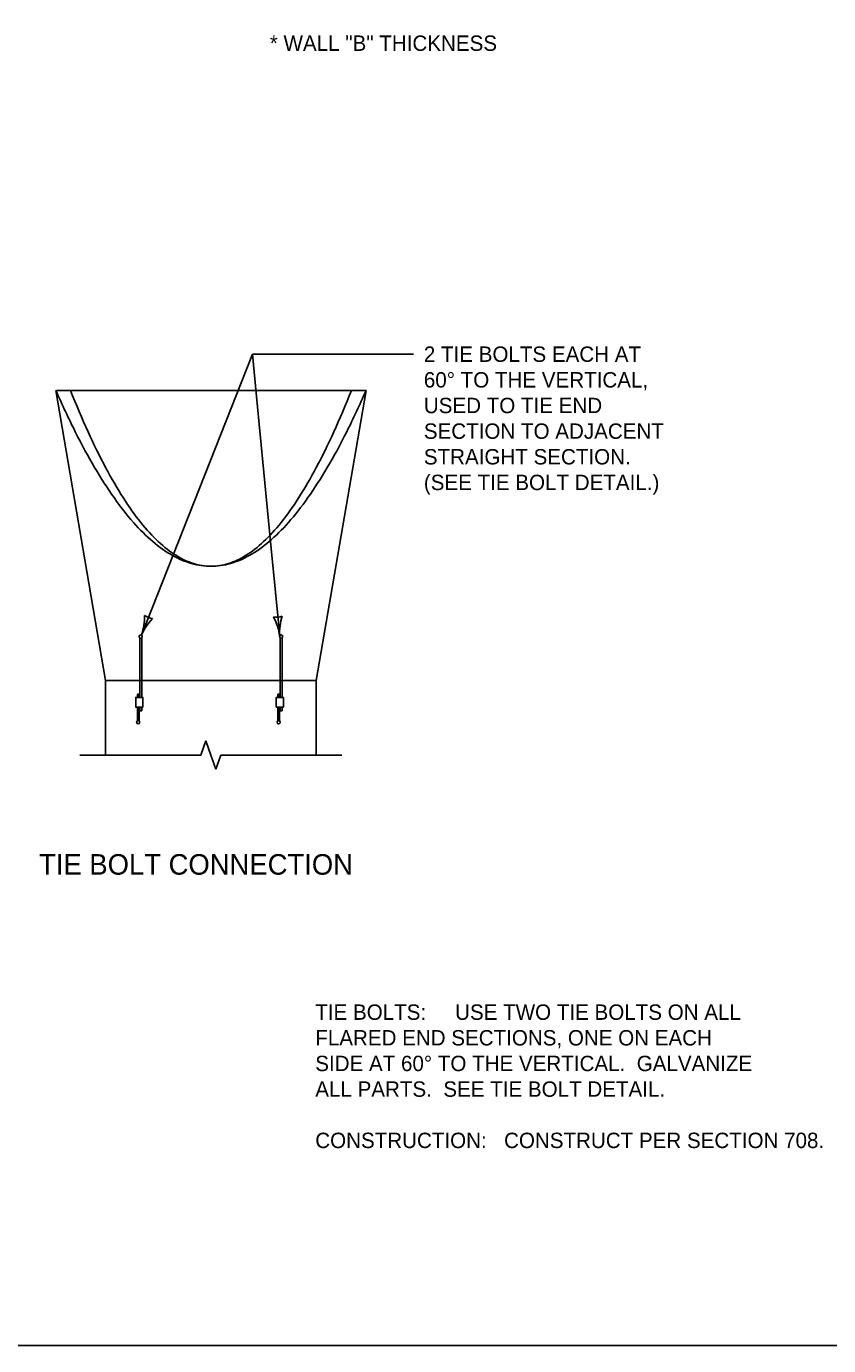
# Model space of a CAD drawing. Extents: x 49991.4 to 50021, y 49987.6 to 50011.4.
# Drawn here: x 50008.67 to 50011.8, y 49987.8 to 49992.94 of the extents above; entities that cross this region are included whole.
import ezdxf

# ---------------------------------------------------------------- set-up
doc = ezdxf.new("R2010")
doc.units = 0
for name, color, linetype in [('Level 1', 7, 'Continuous'), ('Level 2', 7, 'Continuous'), ('Level 3', 7, 'Continuous'), ('Level 6', 7, 'Continuous')]:
    doc.layers.add(name, color=color, linetype=linetype)

msp = doc.modelspace()

# ---------------------------------------------------------------- linework, layer by layer
at = {"layer": 'Level 1'}
for p, q in [((50008.7813, 49991.5224), (50008.9754, 49990.3923)), ((50009.9914, 49991.5224), (50008.7833, 49991.5224)), ((50009.7973, 49990.3923), (50009.9914, 49991.5224)), ((50009.1089, 49990.3264), (50009.1089, 49990.5583)), ((50009.1162, 49990.3264), (50009.1162, 49990.5585)), ((50009.6569, 49990.3264), (50009.6569, 49990.5582)), ((50009.6642, 49990.3264), (50009.6642, 49990.5585)), ((50008.9754, 49990.3923), (50009.7973, 49990.3923)), ((50008.9754, 49990.3923), (50008.9754, 49990.1015)), ((50009.7973, 49990.3923), (50009.7973, 49990.1015)), ((50009.0993, 49990.3264), (50009.0993, 49990.3393)), ((50009.0993, 49990.3393), (50009.1059, 49990.3393)), ((50009.1059, 49990.3264), (50009.1059, 49990.3393)), ((50009.6473, 49990.3264), (50009.6473, 49990.3393)), ((50009.6473, 49990.3393), (50009.6539, 49990.3393)), ((50009.6539, 49990.3264), (50009.6539, 49990.3393)), ((50009.0993, 49990.2349), (50009.0993, 49990.2883)), ((50009.1059, 49990.2346), (50009.1059, 49990.2883)), ((50009.1089, 49990.2744), (50009.1089, 49990.2883)), ((50009.1162, 49990.2744), (50009.1162, 49990.2883)), ((50009.6473, 49990.2349), (50009.6473, 49990.2883)), ((50009.6539, 49990.2345), (50009.6539, 49990.2883)), ((50009.6569, 49990.2744), (50009.6569, 49990.2883)), ((50009.6642, 49990.2744), (50009.6642, 49990.2883)), ((50009.1089, 49990.2744), (50009.1162, 49990.2744)), ((50009.6569, 49990.2744), (50009.6642, 49990.2744))]:
    msp.add_line(p, q, dxfattribs=at)
for points in [[(49999.3835, 49998.9992), (50016.7501, 49998.9992), (50016.7501, 49987.7988), (49999.3835, 49987.7988)], [(50009.1211, 49990.2883), (50009.0933, 49990.2883), (50009.0933, 49990.3264), (50009.1211, 49990.3264)], [(50009.6689, 49990.2883), (50009.6413, 49990.2883), (50009.6413, 49990.3264), (50009.6689, 49990.3264)]]:
    msp.add_lwpolyline(points, close=True, dxfattribs=at)
for centre in [(50009.1124, 49990.5634), (50009.6603, 49990.5634), (50009.1024, 49990.2294), (50009.6503, 49990.2294)]:
    msp.add_circle(centre, 0.00625, dxfattribs=at)
for points in [[(50008.7813, 49991.5224), (50009.3864, 49990.1525), (50009.9914, 49991.5224)], [(50008.8384, 49991.5224), (50009.3864, 49990.1525), (50009.9343, 49991.5224)]]:
    msp.add_open_spline(points, degree=2, dxfattribs=at)
at = {"layer": 'Level 2'}
msp.add_line((49999.3835, 49987.7988), (50016.7501, 49987.7988), dxfattribs=at)
at = {"layer": 'Level 3'}
for p, q in [((50009.1153, 49990.569), (50009.5481, 49991.6644)), ((50009.5481, 49991.6644), (50009.564, 49991.4998)), ((50009.5481, 49991.6644), (50010.1767, 49991.6644)), ((50009.5641, 49991.4998), (50009.6215, 49990.9061)), ((50009.6216, 49990.9061), (50009.6545, 49990.5657))]:
    msp.add_line(p, q, dxfattribs=at)
for centre, radius, start, end in [((50008.8946, 49990.6438), 0.233, 341.2676, 0.5174), ((50009.1624, 49990.6882), 0.0548, 230.5791, 266.3015), ((50009.3185, 49990.4788), 0.2223, 135.8963, 156.0798), ((50009.6422, 49990.6933), 0.0548, 257.6699, 293.3923), ((50009.424, 49990.5318), 0.233, 8.3584, 27.6083), ((50009.8765, 49990.578), 0.2223, 162.9871, 183.1706)]:
    msp.add_arc(centre, radius, start, end, dxfattribs=at)
at = {"layer": 'Level 6'}
for p, q in [((50009.367, 49990.1563), (50009.3475, 49990.1015)), ((50009.367, 49990.1563), (50009.3864, 49990.1015)), ((50008.8754, 49990.1015), (50009.3475, 49990.1015)), ((50009.3864, 49990.1015), (50009.4058, 49990.0467)), ((50009.4253, 49990.1015), (50009.4058, 49990.0467)), ((50009.4253, 49990.1015), (50009.8973, 49990.1015))]:
    msp.add_line(p, q, dxfattribs=at)

# ---------------------------------------------------------------- texts
at = {"layer": 'Level 2'}
for s, height, p in [('* WALL "B" THICKNESS', 0.06, (50009.6159, 49992.847)), ('2 TIE BOLTS EACH AT', 0.06, (50010.2167, 49991.6344)), ('60° TO THE VERTICAL,', 0.06, (50010.2167, 49991.5344)), ('USED TO TIE END', 0.06, (50010.2167, 49991.4344)), ('SECTION TO ADJACENT', 0.06, (50010.2167, 49991.3344)), ('STRAIGHT SECTION.', 0.06, (50010.2167, 49991.2344)), ('(SEE TIE BOLT DETAIL.)', 0.06, (50010.2167, 49991.1344)), ('TIE BOLT CONNECTION', 0.08, (50008.7159, 49989.635)), ('TIE BOLTS:', 0.06, (50009.7932, 49989.069)), ('  USE TWO TIE BOLTS ON ALL', 0.06, (50010.294, 49989.069)), ('FLARED END SECTIONS, ONE ON EACH', 0.06, (50009.7932, 49988.969)), ('SIDE AT 60° TO THE VERTICAL.  GALVANIZE', 0.06, (50009.7932, 49988.869)), ('ALL PARTS.  SEE TIE BOLT DETAIL.', 0.06, (50009.7932, 49988.769)), ('CONSTRUCTION:', 0.06, (50009.7932, 49988.569)), ('  CONSTRUCT PER SECTION 708.', 0.06, (50010.485, 49988.569))]:
    msp.add_text(s, height=height, dxfattribs=at).set_placement(p)

doc.saveas('drawing.dxf')
